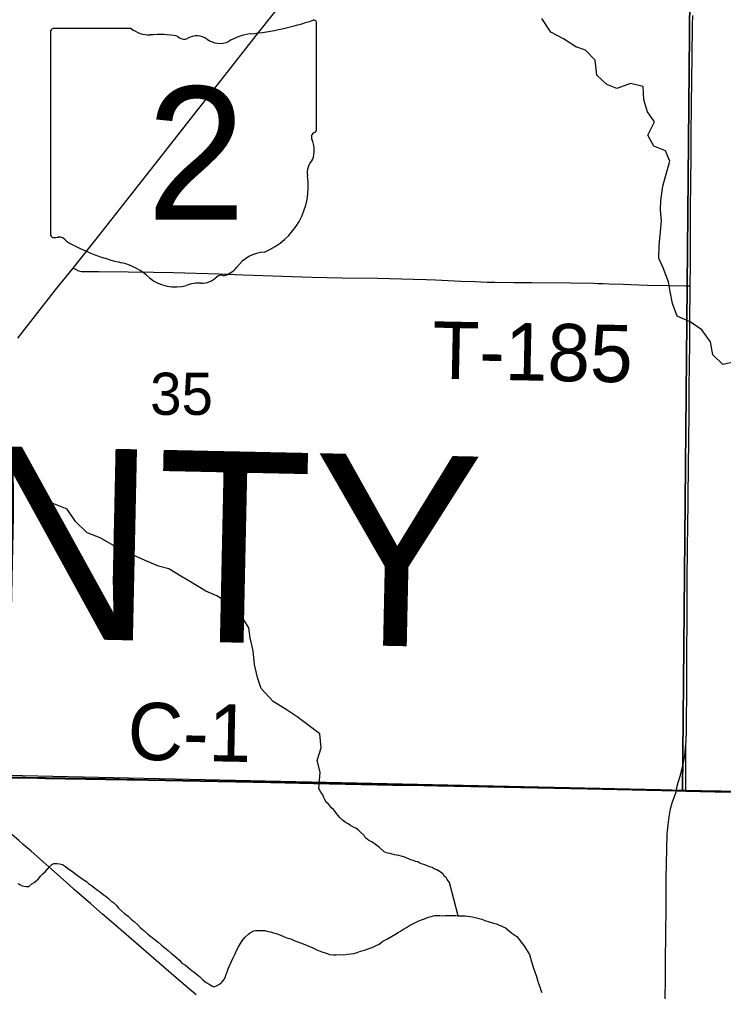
# Model space of a CAD drawing. Extents: x 0 to 34, y 0 to 22.
# Drawn here: x 4.989 to 5.686, y 16.256 to 17.219 of the extents above; entities that cross this region are included whole.
import ezdxf

# ---------------------------------------------------------------- set-up
doc = ezdxf.new("R2010")
doc.units = 0
for name, color, linetype in [('GM_X_County_Road', 7, 'Continuous'), ('GM_X_County_Road_Text', 7, 'Continuous'), ('GM_X_County_Text', 7, 'Continuous'), ('GM_X_Minor_River', 7, 'Continuous'), ('GM_X_Section', 7, 'Continuous'), ('GM_X_Section_Text', 7, 'Continuous'), ('GM_X_State_Location', 7, 'Continuous'), ('GM_X_State_Route', 7, 'Continuous'), ('GM_X_State_Shield', 7, 'Continuous'), ('GM_X_Township_Road', 7, 'Continuous'), ('GM_X_Township_Road_Text', 7, 'Continuous'), ('SH_Cut_Line', 7, 'Continuous')]:
    doc.layers.add(name, color=color, linetype=linetype)

msp = doc.modelspace()

# ---------------------------------------------------------------- linework, layer by layer
at = {"layer": 'GM_X_County_Road'}
for p, q in [((5.00655, 16.46706), (5.01451, 16.46693)), ((5.38894, 16.45988), (5.39195, 16.45982))]:
    msp.add_line(p, q, dxfattribs=at)
for points in [[(5.65345, 16.95502), (5.65361, 16.97673), (5.6538, 17.01155), (5.6538, 17.01963), (5.65382, 17.03517), (5.65397, 17.05381), (5.65406, 17.06438), (5.65421, 17.07743), (5.65443, 17.10478), (5.65474, 17.13523), (5.6552, 17.18246), (5.65574, 17.2129), (5.65593, 17.22285)], [(5.64916, 16.50089), (5.64937, 16.50377), (5.64958, 16.51429), (5.64993, 16.56153), (5.65017, 16.59884), (5.65039, 16.61748), (5.65052, 16.6585), (5.65086, 16.69891), (5.651, 16.71383), (5.6514, 16.74366), (5.65166, 16.77723), (5.6519, 16.80085), (5.65222, 16.82943), (5.65228, 16.85429), (5.65265, 16.87605), (5.65293, 16.89842), (5.65307, 16.9208), (5.65343, 16.95126), (5.65345, 16.95502)], [(5.63969, 16.4545), (5.6403, 16.45794), (5.64156, 16.46303), (5.64372, 16.47032), (5.64634, 16.48115), (5.64795, 16.48965), (5.64888, 16.497), (5.64916, 16.50089)], [(5.64915, 16.45429), (5.64914, 16.45684), (5.64914, 16.45986), (5.64903, 16.4693), (5.64908, 16.48052), (5.64916, 16.50089)], [(5.16387, 16.2526), (5.14863, 16.2654), (5.13162, 16.27996), (5.09455, 16.31218), (5.08236, 16.3228), (5.07108, 16.33257), (5.05935, 16.34276), (5.04292, 16.35702), (5.03823, 16.36112), (5.02892, 16.36938), (5.0122, 16.38421), (5.00577, 16.39), (5.00029, 16.39473), (4.99233, 16.40162), (4.98814, 16.40529), (4.98107, 16.41134), (4.97735, 16.41462), (4.97552, 16.41625), (4.97227, 16.41912), (4.95637, 16.43301), (4.94792, 16.44035), (4.93994, 16.44727), (4.92452, 16.46082), (4.91549, 16.46876)], [(4.91549, 16.46876), (4.95484, 16.46793), (5.00655, 16.46706)], [(5.01451, 16.46693), (5.07418, 16.46593), (5.11582, 16.4651), (5.23764, 16.46276), (5.28054, 16.46208), (5.35885, 16.46043), (5.38894, 16.45988)], [(5.39195, 16.45982), (5.40298, 16.45962), (5.55153, 16.45651), (5.63969, 16.4545)], [(5.62568, 15.94388), (5.62587, 15.95356), (5.62617, 15.98465), (5.62676, 16.04185), (5.62715, 16.07542), (5.6273, 16.12142), (5.6276, 16.15313), (5.62806, 16.18981), (5.62845, 16.23084), (5.62889, 16.28617), (5.62947, 16.33902), (5.62971, 16.36824), (5.63014, 16.39683), (5.63068, 16.41171), (5.63144, 16.42096), (5.63251, 16.42891), (5.634, 16.43679), (5.63556, 16.44274), (5.63738, 16.44795), (5.63969, 16.4545)]]:
    msp.add_lwpolyline(points, dxfattribs=at)
at = {"layer": 'GM_X_County_Text'}
for points in [[(4.9546, 16.46848), (5.07394, 16.46648), (5.11559, 16.46566), (5.23741, 16.46331), (5.2803, 16.46264), (5.35861, 16.46098), (5.40275, 16.46017), (5.55129, 16.45706), (5.63945, 16.45506), (5.64891, 16.45484), (5.67745, 16.45419), (5.74272, 16.45282)], [(5.74272, 16.45282), (5.67745, 16.45419), (5.64891, 16.45484), (5.63945, 16.45506), (5.55129, 16.45706), (5.40275, 16.46017), (5.35861, 16.46098), (5.2803, 16.46264), (5.23741, 16.46331), (5.11559, 16.46566), (5.07394, 16.46648), (4.9546, 16.46848)]]:
    msp.add_lwpolyline(points, dxfattribs=at)
at = {"layer": 'GM_X_Minor_River'}
for points in [[(5.69807, 16.87978), (5.68588, 16.87698), (5.67583, 16.88665), (5.67343, 16.89959), (5.66493, 16.91151), (5.65333, 16.91932), (5.64054, 16.92488), (5.63586, 16.93749), (5.63343, 16.94929), (5.63173, 16.95918), (5.62668, 16.97293), (5.62232, 16.98249), (5.62256, 16.995), (5.62397, 17.00901), (5.62493, 17.0196), (5.624, 17.03024), (5.62418, 17.03972), (5.62635, 17.0537), (5.62881, 17.06352), (5.63327, 17.07859), (5.62892, 17.08892), (5.61725, 17.09332), (5.6114, 17.10443), (5.6181, 17.11757), (5.61109, 17.12756), (5.60752, 17.13939), (5.60664, 17.15268), (5.59419, 17.15557), (5.58082, 17.15052), (5.57065, 17.15451), (5.56097, 17.1638), (5.55936, 17.17862), (5.5497, 17.18866), (5.5399, 17.19189), (5.52792, 17.1997), (5.51516, 17.2064), (5.50631, 17.21984)], [(5.28525, 16.45679), (5.2868, 16.47329), (5.28357, 16.4847), (5.28761, 16.49714), (5.28636, 16.5112), (5.2744, 16.52015), (5.26393, 16.52794), (5.25382, 16.53458), (5.23996, 16.5432), (5.22807, 16.55594), (5.22449, 16.56701), (5.2217, 16.57996), (5.22044, 16.59326), (5.21728, 16.60621), (5.21595, 16.6161), (5.20934, 16.62685), (5.19745, 16.63959), (5.18433, 16.64781), (5.17343, 16.65257), (5.15994, 16.6608), (5.14869, 16.66746), (5.13669, 16.67452), (5.12651, 16.67738), (5.11334, 16.68294), (5.10056, 16.6885), (5.09078, 16.69286), (5.07953, 16.69914), (5.06865, 16.70542), (5.05585, 16.71022), (5.04431, 16.72144), (5.03583, 16.73374), (5.02265, 16.73893), (5.00941, 16.74032), (4.99789, 16.7523), (4.99353, 16.76224), (4.98156, 16.77082)], [(5.42355, 16.33094), (5.41483, 16.36381), (5.41263, 16.36691), (5.41153, 16.36883), (5.40966, 16.37002), (5.40857, 16.37194), (5.40672, 16.37388), (5.40409, 16.37546), (5.40221, 16.37627), (5.39959, 16.37747), (5.39772, 16.37865), (5.39508, 16.37948), (5.39207, 16.38069), (5.38943, 16.38151), (5.38717, 16.38232), (5.38529, 16.38313), (5.38342, 16.38431), (5.38153, 16.38473), (5.3789, 16.38556), (5.37664, 16.38637), (5.37438, 16.38718), (5.3725, 16.38799), (5.37062, 16.38879), (5.36685, 16.39002), (5.36458, 16.39045), (5.36269, 16.39088), (5.36043, 16.39131), (5.35816, 16.39174), (5.3559, 16.39256), (5.35326, 16.393), (5.35025, 16.39421), (5.34541, 16.3985), (5.3428, 16.40047), (5.34019, 16.40243), (5.33795, 16.404), (5.3357, 16.40519), (5.33345, 16.40639), (5.33122, 16.40834), (5.33012, 16.41026), (5.32679, 16.41376), (5.32456, 16.41571), (5.32194, 16.41767), (5.31894, 16.41888), (5.31669, 16.42046), (5.31445, 16.42203), (5.31145, 16.42362), (5.30884, 16.42558), (5.30625, 16.4283), (5.3044, 16.43024), (5.30292, 16.43218), (5.30145, 16.43411), (5.29998, 16.43604), (5.29812, 16.43761), (5.29664, 16.43954), (5.29479, 16.44148), (5.29219, 16.44383), (5.29112, 16.44689), (5.29003, 16.44881), (5.28931, 16.45073), (5.28748, 16.45343), (5.28521, 16.45684)], [(4.98733, 16.36293), (4.9892, 16.36175), (4.99145, 16.36056), (4.99334, 16.36013), (4.99523, 16.35971), (4.99789, 16.36002), (5.00099, 16.36261), (5.00329, 16.3637), (5.00523, 16.36555), (5.00756, 16.36739), (5.00951, 16.37), (5.01223, 16.3726), (5.01418, 16.37445), (5.01613, 16.37668), (5.01847, 16.37929), (5.0208, 16.38151), (5.02272, 16.38261), (5.02576, 16.38253), (5.02841, 16.38247), (5.03143, 16.38164), (5.03442, 16.37967)], [(5.03442, 16.37967), (5.03628, 16.37811), (5.03852, 16.37653), (5.04113, 16.37457), (5.04337, 16.373), (5.04599, 16.37104), (5.04934, 16.3683), (5.05196, 16.36672), (5.05495, 16.36475), (5.05718, 16.3628), (5.06017, 16.36083), (5.06315, 16.35848), (5.06614, 16.35613), (5.06913, 16.35416), (5.07173, 16.35182), (5.07472, 16.34985), (5.07695, 16.3479), (5.07918, 16.34557), (5.08217, 16.34359), (5.08439, 16.34126), (5.08698, 16.33854), (5.08996, 16.33581), (5.09293, 16.33309), (5.09628, 16.33035), (5.09925, 16.32762), (5.10261, 16.32488), (5.10558, 16.32215), (5.10854, 16.31904), (5.1119, 16.3163), (5.11599, 16.31279), (5.12605, 16.30457), (5.1294, 16.30183), (5.13275, 16.2991), (5.13611, 16.29636), (5.13946, 16.29362), (5.14244, 16.29127), (5.14504, 16.28893), (5.14727, 16.28698), (5.14948, 16.28389), (5.15323, 16.2819), (5.15546, 16.27995), (5.15769, 16.27799), (5.15993, 16.27642), (5.16179, 16.27486), (5.16366, 16.27329), (5.16701, 16.27056), (5.17035, 16.26744), (5.17222, 16.26588), (5.17446, 16.2643), (5.1767, 16.26311), (5.17933, 16.26153), (5.18158, 16.26034), (5.18465, 16.26178), (5.18696, 16.26325), (5.18928, 16.26509), (5.19123, 16.26732), (5.19242, 16.26957), (5.19364, 16.27296), (5.19444, 16.27484), (5.19566, 16.27823), (5.19687, 16.28124), (5.19848, 16.285), (5.20047, 16.28913), (5.20247, 16.29327), (5.20408, 16.29703), (5.20567, 16.30003), (5.20882, 16.30489), (5.21001, 16.30714), (5.21235, 16.30974), (5.21584, 16.31308), (5.21777, 16.31417), (5.22085, 16.316), (5.22275, 16.31634), (5.22655, 16.31625), (5.2292, 16.31618), (5.23186, 16.31612), (5.23488, 16.31529), (5.23752, 16.31484), (5.24054, 16.31401), (5.24318, 16.31319), (5.24657, 16.31197), (5.25033, 16.31036), (5.25372, 16.30914), (5.25748, 16.30791), (5.26161, 16.30592), (5.26726, 16.30388), (5.2714, 16.30227), (5.27553, 16.30065), (5.27929, 16.29904), (5.28342, 16.29705), (5.28831, 16.29503), (5.29246, 16.29379), (5.29622, 16.29256), (5.29963, 16.2921), (5.30267, 16.29203), (5.30571, 16.29234), (5.31026, 16.29223), (5.3137, 16.29291), (5.31712, 16.29321), (5.32016, 16.29352), (5.32323, 16.29458)], [(5.32323, 16.29458), (5.32667, 16.29564), (5.33049, 16.29669), (5.33432, 16.29812), (5.33815, 16.29954), (5.3416, 16.30098), (5.34506, 16.3028), (5.34893, 16.30575), (5.35353, 16.30792), (5.36124, 16.31267), (5.36393, 16.31413), (5.36624, 16.31559), (5.36932, 16.31742), (5.3724, 16.31924), (5.3751, 16.32108), (5.37779, 16.32253), (5.38049, 16.32399), (5.38432, 16.3258), (5.38701, 16.32687), (5.39007, 16.32794), (5.39313, 16.32901), (5.39543, 16.32971), (5.3981, 16.33041), (5.4004, 16.33111), (5.40305, 16.33105), (5.40533, 16.331), (5.40798, 16.33093), (5.41065, 16.33125), (5.41406, 16.33117), (5.41824, 16.33107), (5.42127, 16.331), (5.42355, 16.33094), (5.4262, 16.33088), (5.4281, 16.33084), (5.43038, 16.33078), (5.43265, 16.33035), (5.43492, 16.33029), (5.43719, 16.32986), (5.44021, 16.32903), (5.44286, 16.32859), (5.447, 16.32735), (5.45001, 16.32614), (5.45416, 16.3249), (5.4583, 16.32366), (5.46132, 16.32283), (5.46395, 16.32163), (5.46621, 16.32082), (5.46809, 16.32001), (5.47034, 16.31882), (5.4722, 16.31725), (5.47444, 16.31568), (5.47667, 16.31373), (5.47966, 16.31176), (5.48153, 16.3102), (5.48411, 16.3071), (5.48558, 16.30516), (5.48743, 16.30284), (5.48927, 16.30052), (5.49402, 16.29243), (5.49508, 16.28898), (5.49684, 16.28324), (5.49826, 16.27903), (5.49967, 16.27444), (5.5011, 16.27061), (5.50215, 16.26717), (5.50321, 16.26372), (5.50427, 16.26028), (5.50534, 16.25721), (5.50642, 16.25491)]]:
    msp.add_lwpolyline(points, dxfattribs=at)
at = {"layer": 'GM_X_Section'}
for points in [[(4.66052, 17.47484), (5.65514, 17.45551), (5.64591, 16.45512), (5.62401, 16.4556), (4.6453, 16.47708)], [(5.65514, 17.45551), (6.66543, 17.44151), (6.6455, 16.43781), (5.64591, 16.45512)]]:
    msp.add_lwpolyline(points, close=True, dxfattribs=at)
at = {"layer": 'GM_X_State_Route'}
msp.add_lwpolyline([(4.98702, 16.90306), (5.02455, 16.95107), (5.04176, 16.97261), (5.06957, 17.00744), (5.09864, 17.04471), (5.12668, 17.0804), (5.16007, 17.12297), (5.18488, 17.15409), (5.22334, 17.20296), (5.27778, 17.27169)], dxfattribs=at)
at = {"layer": 'GM_X_State_Shield'}
for p, q in [((5.28315, 17.11034), (5.28315, 17.21502)), ((5.01949, 17.20662), (5.01949, 17.0065)), ((5.0993, 17.21006), (5.02208, 17.21006)), ((5.28313, 17.11036), (5.28315, 17.11034))]:
    msp.add_line(p, q, dxfattribs=at)
for centre, radius, start, end in [((5.18923, 17.48289), 0.27962, 275.84447, 288.90645), ((5.28023, 17.21546), 0.00294, 351.86209, 97.738), ((5.02251, 17.20704), 0.00305, 98.1301, 188.1301), ((5.11769, 17.23329), 0.02963, 231.61951, 271.11188), ((5.12751, 17.09771), 0.10636, 80.48669, 94.98827), ((5.2249, 17.14894), 0.05625, 97.34618, 120.76885), ((5.15166, 17.20808), 0.00855, 219.79206, 297.10237), ((5.1642, 17.18495), 0.01777, 54.46668, 119.14113), ((5.18714, 17.21668), 0.02138, 233.85621, 294.82819), ((5.28002, 17.10993), 0.00314, 289.60381, 7.73413), ((5.28247, 17.10265), 0.00454, 107.94398, 210.33697), ((5.25357, 17.08942), 0.02727, 340.03296, 23.64957), ((5.29367, 17.06653), 0.01984, 136.8065, 186.92959), ((5.20489, 17.05321), 0.06994, 292.30889, 8.98584), ((5.02253, 17.00606), 0.00308, 171.95839, 258.30661), ((5.023, 17.02653), 0.02352, 267.33899, 280.60386), ((5.02781, 16.99495), 0.00848, 29.74838, 93.27175), ((5.13487, 17.17475), 0.20192, 240.41292, 257.1985), ((5.23438, 16.95031), 0.0383, 94.40312, 142.57675), ((5.07467, 16.91659), 0.06318, 47.18416, 75.83597), ((5.18585, 16.9871), 0.0226, 282.87319, 323.27711), ((5.16909, 16.97897), 0.02136, 268.77702, 315.54927), ((5.18842, 16.95959), 0.00601, 65.75173, 132.64842), ((5.143, 16.99396), 0.04009, 230.70037, 286.29184), ((5.16617, 16.92477), 0.03294, 85.69512, 111.20995)]:
    msp.add_arc(centre, radius, start, end, dxfattribs=at)
at = {"layer": 'GM_X_Township_Road'}
for p, q in [((5.00655, 16.46706), (5.01451, 16.46693)), ((5.38894, 16.45988), (5.39195, 16.45982)), ((5.63969, 16.4545), (5.64915, 16.45429))]:
    msp.add_line(p, q, dxfattribs=at)
for points in [[(5.04176, 16.97261), (5.04415, 16.97145), (5.04636, 16.97037), (5.04754, 16.96996), (5.04875, 16.9696), (5.05026, 16.96941), (5.05243, 16.96933), (5.06734, 16.9692), (5.09656, 16.96895), (5.12143, 16.96858), (5.14132, 16.96818), (5.18669, 16.96679), (5.2103, 16.96606), (5.27865, 16.96381), (5.30849, 16.96307), (5.34393, 16.96255), (5.37874, 16.96167), (5.39177, 16.96147), (5.40108, 16.96115), (5.42604, 16.9598), (5.43979, 16.95922), (5.45228, 16.95883), (5.45962, 16.9587), (5.47872, 16.95845), (5.49657, 16.9582), (5.5347, 16.95789), (5.55768, 16.9576), (5.5618, 16.95753), (5.56716, 16.95733), (5.57314, 16.95713), (5.58742, 16.95663), (5.60232, 16.95616), (5.61102, 16.95587), (5.63215, 16.95536), (5.64893, 16.95509), (5.65345, 16.95502)], [(4.91549, 16.46876), (4.95484, 16.46793), (5.00655, 16.46706)], [(5.01451, 16.46693), (5.07418, 16.46593), (5.11582, 16.4651), (5.23764, 16.46276), (5.28054, 16.46208), (5.35885, 16.46043), (5.38894, 16.45988)], [(5.39195, 16.45982), (5.40298, 16.45962), (5.55153, 16.45651), (5.63969, 16.4545)], [(5.64915, 16.45429), (5.67769, 16.45363), (5.74295, 16.45227), (5.79267, 16.45146), (5.83495, 16.45087), (5.89773, 16.44995), (5.9406, 16.4494), (6.04192, 16.44805), (6.08355, 16.44715), (6.22883, 16.4446), (6.26239, 16.44416), (6.34799, 16.44256), (6.38544, 16.44205), (6.48983, 16.43966), (6.53831, 16.43878), (6.59363, 16.43763), (6.63403, 16.43675), (6.63919, 16.4366), (6.65104, 16.43623)]]:
    msp.add_lwpolyline(points, dxfattribs=at)
at = {"layer": 'SH_Cut_Line'}
for points in [[(5.74272, 16.45282), (5.67745, 16.45419), (5.64891, 16.45484), (5.63945, 16.45506), (5.55129, 16.45706), (5.40275, 16.46017), (5.35861, 16.46098), (5.2803, 16.46264), (5.23741, 16.46331), (5.11559, 16.46566), (5.07394, 16.46648), (4.9546, 16.46848)], [(4.9546, 16.46848), (5.07394, 16.46648), (5.11559, 16.46566), (5.23741, 16.46331), (5.2803, 16.46264), (5.35861, 16.46098), (5.40275, 16.46017), (5.55129, 16.45706), (5.63945, 16.45506), (5.64891, 16.45484), (5.67745, 16.45419), (5.74272, 16.45282)]]:
    msp.add_lwpolyline(points, dxfattribs=at)

# ---------------------------------------------------------------- texts
at = {"layer": 'GM_X_County_Road_Text'}
msp.add_text('C-1', height=0.056818, rotation=358.87241, dxfattribs=at).set_placement((5.0955, 16.48558))
at = {"layer": 'GM_X_County_Text'}
msp.add_text('WILLIAMS COUNTY', height=0.1893939, rotation=358.77482, dxfattribs=at).set_placement((3.09586, 16.64661))
at = {"layer": 'GM_X_Section_Text'}
msp.add_text('35', height=0.041856, rotation=0.00001, dxfattribs=at).set_placement((5.11816, 16.82717))
at = {"layer": 'GM_X_State_Location'}
for s, p in [('s', (5.14835, 17.09325)), ('r', (5.14834, 17.09325))]:
    msp.add_text(s, height=0.000189, dxfattribs=at).set_placement(p)
msp.add_text('2', height=0.000189, rotation=0.00001, dxfattribs=at).set_placement((5.11982, 17.07948))
at = {"layer": 'GM_X_State_Shield'}
msp.add_text('2', height=0.13184, dxfattribs=at).set_placement((5.11473, 17.02061))
at = {"layer": 'GM_X_Township_Road_Text'}
msp.add_text('T-185', height=0.056818, rotation=358.8788, dxfattribs=at).set_placement((5.39746, 16.86313))

doc.saveas('drawing.dxf')
